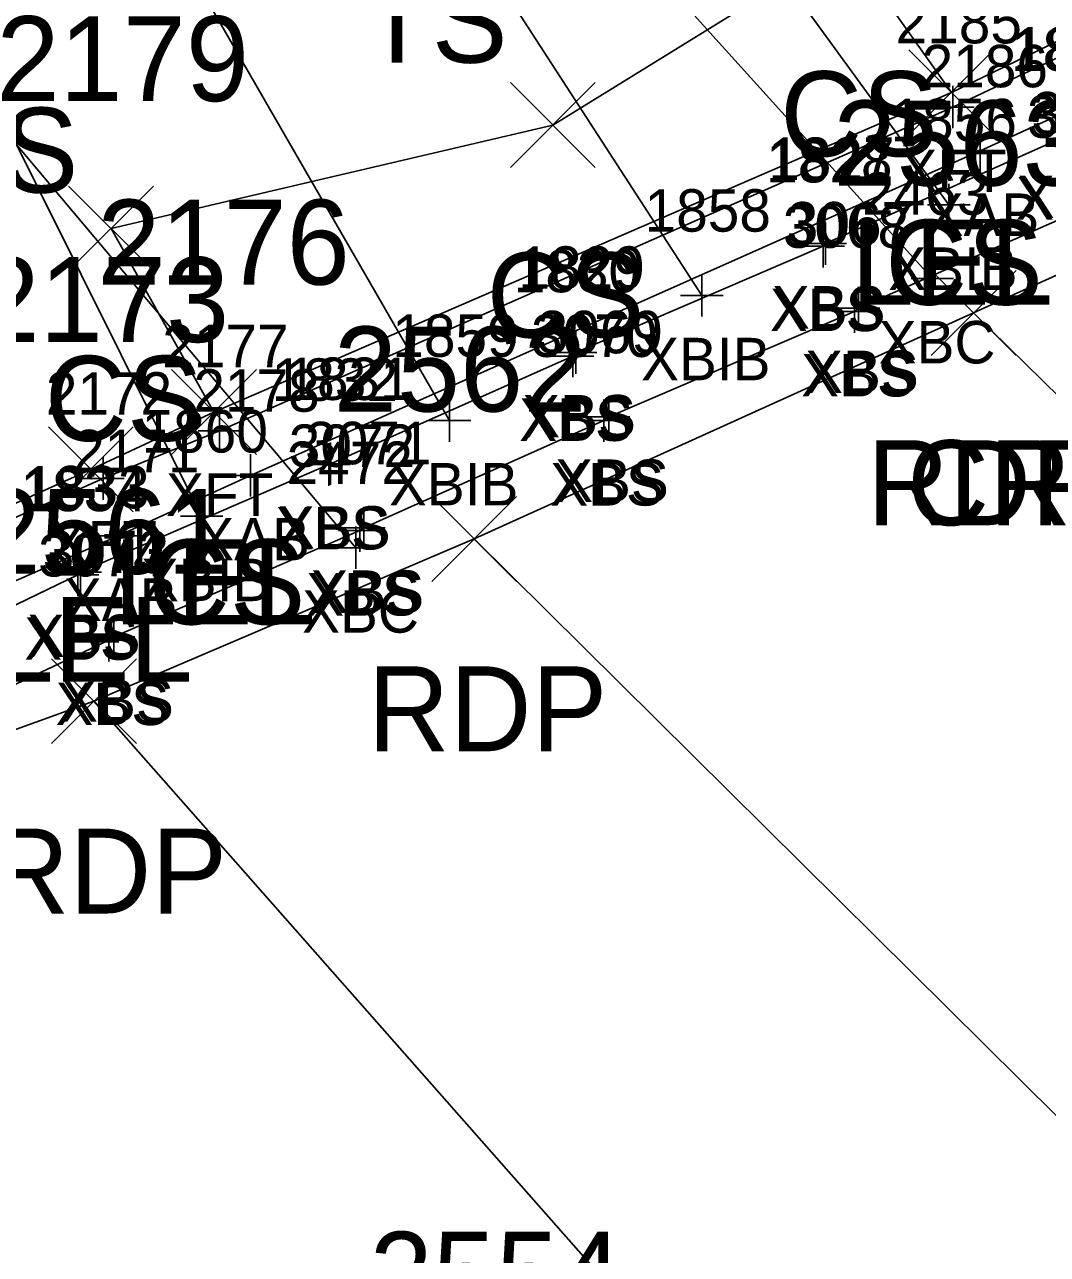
# Model space of a CAD drawing. Extents: x 1504228 to 1506103, y 437717 to 440106.
# Drawn here: x 1505241.43 to 1505265.52, y 438136.49 to 438165.45 of the extents above; entities that cross this region are included whole.
import ezdxf

# ---------------------------------------------------------------- set-up
doc = ezdxf.new("R2010")
doc.units = 0
for name, color, linetype in [('B_A', 7, 'Continuous'), ('B_I', 7, 'Continuous'), ('B_TIC', 7, 'Continuous'), ('BB', 7, 'Continuous'), ('BELB', 7, 'Continuous'), ('BFT', 7, 'Continuous'), ('BSE', 7, 'Continuous'), ('BSUBM', 7, 'Continuous'), ('L_A', 7, 'Continuous'), ('L_I', 7, 'Continuous'), ('L_TIC', 7, 'Continuous'), ('LARO', 7, 'Continuous'), ('LELB', 7, 'Continuous'), ('P_A', 7, 'Continuous'), ('P_I', 7, 'Continuous'), ('P_TIC', 7, 'Continuous'), ('PET', 7, 'Continuous'), ('PRC', 7, 'Continuous')]:
    doc.layers.add(name, color=color, linetype=linetype)

msp = doc.modelspace()

# ---------------------------------------------------------------- linework, layer by layer
at = {"layer": 'B_TIC'}
for p, q in [((1505263.294, 438163.511), (1505263.37, 438163.511)), ((1505263.935, 438162.477), (1505264.01, 438162.477)), ((1505263.201, 438161.205), (1505263.277, 438161.205)), ((1505260.245, 438160.235), (1505260.32, 438160.235)), ((1505260.292, 438160.295), (1505260.368, 438160.295)), ((1505262.812, 438159.474), (1505262.887, 438159.474)), ((1505257.382, 438159.077), (1505257.458, 438159.077)), ((1505261.076, 438158.776), (1505261.152, 438158.776)), ((1505260.982, 438158.696), (1505261.058, 438158.696)), ((1505254.343, 438157.649), (1505254.419, 438157.649)), ((1505254.414, 438157.731), (1505254.49, 438157.731)), ((1505255.189, 438156.213), (1505255.265, 438156.213)), ((1505246.023, 438155.885), (1505246.098, 438155.885)), ((1505251.445, 438156.129), (1505251.52, 438156.129)), ((1505255.073, 438156.127), (1505255.149, 438156.127)), ((1505248.599, 438155.093), (1505248.675, 438155.093)), ((1505248.638, 438155.113), (1505248.714, 438155.113)), ((1505243.281, 438154.766), (1505243.357, 438154.766)), ((1505246.757, 438154.837), (1505246.832, 438154.837)), ((1505245.603, 438153.876), (1505245.678, 438153.876)), ((1505249.326, 438153.537), (1505249.402, 438153.537)), ((1505249.426, 438153.6), (1505249.502, 438153.6)), ((1505243.64, 438153.412), (1505243.716, 438153.412)), ((1505249.234, 438153.134), (1505249.31, 438153.134)), ((1505242.686, 438152.495), (1505242.762, 438152.495)), ((1505242.75, 438152.562), (1505242.825, 438152.562)), ((1505243.422, 438150.958), (1505243.498, 438150.958)), ((1505243.532, 438151.037), (1505243.608, 438151.037))]:
    msp.add_line(p, q, dxfattribs=at)
for points in [[(1505263.291, 438163.011), (1505263.291, 438164.011)], [(1505262.791, 438163.511), (1505263.791, 438163.511)], [(1505263.932, 438161.977), (1505263.932, 438162.977)], [(1505263.432, 438162.477), (1505264.432, 438162.477)], [(1505263.198, 438160.705), (1505263.198, 438161.705)], [(1505262.698, 438161.205), (1505263.698, 438161.205)], [(1505260.289, 438159.795), (1505260.289, 438160.795)], [(1505260.241, 438159.735), (1505260.241, 438160.735)], [(1505259.741, 438160.235), (1505260.741, 438160.235)], [(1505259.789, 438160.295), (1505260.789, 438160.295)], [(1505262.808, 438158.974), (1505262.808, 438159.974)], [(1505257.379, 438158.577), (1505257.379, 438159.577)], [(1505262.308, 438159.474), (1505263.308, 438159.474)], [(1505256.879, 438159.077), (1505257.879, 438159.077)], [(1505260.979, 438158.196), (1505260.979, 438159.196)], [(1505261.073, 438158.276), (1505261.073, 438159.276)], [(1505260.573, 438158.776), (1505261.573, 438158.776)], [(1505260.479, 438158.696), (1505261.479, 438158.696)], [(1505254.411, 438157.231), (1505254.411, 438158.231)], [(1505254.34, 438157.149), (1505254.34, 438158.149)], [(1505253.84, 438157.649), (1505254.84, 438157.649)], [(1505253.911, 438157.731), (1505254.911, 438157.731)], [(1505251.441, 438155.629), (1505251.441, 438156.629)], [(1505255.07, 438155.627), (1505255.07, 438156.627)], [(1505255.186, 438155.713), (1505255.186, 438156.713)], [(1505246.019, 438155.385), (1505246.019, 438156.385)], [(1505254.686, 438156.213), (1505255.686, 438156.213)], [(1505245.519, 438155.885), (1505246.519, 438155.885)], [(1505250.941, 438156.129), (1505251.941, 438156.129)], [(1505254.57, 438156.127), (1505255.57, 438156.127)], [(1505248.596, 438154.593), (1505248.596, 438155.593)], [(1505248.635, 438154.613), (1505248.635, 438155.613)], [(1505246.753, 438154.337), (1505246.753, 438155.337)], [(1505243.278, 438154.266), (1505243.278, 438155.266)], [(1505248.096, 438155.093), (1505249.096, 438155.093)], [(1505248.135, 438155.113), (1505249.135, 438155.113)], [(1505242.778, 438154.766), (1505243.778, 438154.766)], [(1505246.253, 438154.837), (1505247.253, 438154.837)], [(1505245.599, 438153.376), (1505245.599, 438154.376)], [(1505243.637, 438152.912), (1505243.637, 438153.912)], [(1505245.099, 438153.876), (1505246.099, 438153.876)], [(1505249.323, 438153.037), (1505249.323, 438154.037)], [(1505249.423, 438153.1), (1505249.423, 438154.1)], [(1505248.823, 438153.537), (1505249.823, 438153.537)], [(1505248.923, 438153.6), (1505249.923, 438153.6)], [(1505249.231, 438152.634), (1505249.231, 438153.634)], [(1505243.137, 438153.412), (1505244.137, 438153.412)], [(1505242.683, 438151.995), (1505242.683, 438152.995)], [(1505242.746, 438152.062), (1505242.746, 438153.062)], [(1505248.731, 438153.134), (1505249.731, 438153.134)], [(1505242.183, 438152.495), (1505243.183, 438152.495)], [(1505242.246, 438152.562), (1505243.246, 438152.562)], [(1505243.529, 438150.537), (1505243.529, 438151.537)], [(1505243.419, 438150.458), (1505243.419, 438151.458)], [(1505242.919, 438150.958), (1505243.919, 438150.958)], [(1505243.029, 438151.037), (1505244.029, 438151.037)]]:
    msp.add_lwpolyline(points, dxfattribs=at)
at = {"layer": 'BB'}
for points in [[(1505263.198, 438161.205), (1505236.12, 438198.358)], [(1505257.379, 438159.077), (1505232.798, 438197.013)], [(1505251.441, 438156.129), (1505228.857, 438195.264)], [(1505245.599, 438153.876), (1505225.746, 438193.733)]]:
    msp.add_lwpolyline(points, dxfattribs=at)
at = {"layer": 'BELB'}
for points in [[(1505262.808, 438159.474), (1505244.884, 438179.311), (1505229.042, 438198.247), (1505213.306, 438219.16), (1505200.113, 438237.757)], [(1505189.093, 438232.07), (1505202.074, 438213.317), (1505217.089, 438192.519), (1505234.002, 438171.224), (1505249.231, 438153.134)]]:
    msp.add_lwpolyline(points, dxfattribs=at)
at = {"layer": 'BFT'}
msp.add_lwpolyline([(1505211.711, 438138.978), (1505211.593, 438140.8), (1505215.376, 438142.417), (1505230.303, 438149.002), (1505243.278, 438154.766), (1505246.019, 438155.885), (1505263.291, 438163.511), (1505271.064, 438167.183), (1505276.649, 438169.866), (1505288.201, 438174.699), (1505288.73, 438173.49)], dxfattribs=at)
at = {"layer": 'BSE'}
for points in [[(1505266.037, 438162.863), (1505260.289, 438160.295), (1505260.241, 438160.235), (1505254.411, 438157.731), (1505254.34, 438157.649), (1505248.635, 438155.113), (1505248.596, 438155.093), (1505242.746, 438152.562), (1505242.683, 438152.495), (1505239.318, 438150.871)], [(1505266.757, 438161.287), (1505261.073, 438158.776), (1505260.979, 438158.696), (1505255.186, 438156.213), (1505255.07, 438156.127), (1505249.423, 438153.6), (1505249.323, 438153.537), (1505243.529, 438151.037), (1505243.419, 438150.958), (1505240.07, 438149.38)]]:
    msp.add_lwpolyline(points, dxfattribs=at)
at = {"layer": 'BSUBM'}
msp.add_lwpolyline([(1505214.761, 438127.389), (1505213.65, 438134.809), (1505212.657, 438139.975), (1505231.134, 438147.944), (1505243.637, 438153.412), (1505246.753, 438154.837), (1505263.932, 438162.477), (1505271.425, 438165.886), (1505277.465, 438168.561), (1505287.974, 438173.167), (1505291.052, 438171.05), (1505297.268, 438166.649), (1505302.136, 438162.984), (1505307.468, 438159.403), (1505307.306, 438158.962)], dxfattribs=at)
at = {"layer": 'L_TIC'}
for points in [[(1505262.257, 438162.856), (1505264.257, 438164.856)], [(1505264.257, 438162.856), (1505262.257, 438164.856)], [(1505262.257, 438162.856), (1505264.257, 438164.856)], [(1505264.257, 438162.856), (1505262.257, 438164.856)], [(1505252.871, 438162.088), (1505254.871, 438164.088)], [(1505254.871, 438162.088), (1505252.871, 438164.088)], [(1505242.468, 438159.651), (1505244.468, 438161.651)], [(1505244.468, 438159.651), (1505242.468, 438161.651)], [(1505244.889, 438155.33), (1505246.889, 438157.33)], [(1505246.889, 438155.33), (1505244.889, 438157.33)], [(1505244.889, 438155.33), (1505246.889, 438157.33)], [(1505246.889, 438155.33), (1505244.889, 438157.33)], [(1505241.992, 438153.978), (1505243.992, 438155.978)], [(1505243.992, 438153.978), (1505241.992, 438155.978)]]:
    msp.add_lwpolyline(points, dxfattribs=at)
at = {"layer": 'LARO'}
msp.add_lwpolyline([(1505211.067, 438140.867), (1505215.631, 438142.954), (1505229.653, 438148.999), (1505242.992, 438154.978), (1505245.889, 438156.33), (1505263.257, 438163.856), (1505270.634, 438167.43), (1505277.265, 438170.598), (1505281.289, 438172.305), (1505281.518, 438175.58), (1505285.106, 438180.489), (1505287.419, 438180.921)], dxfattribs=at)
at = {"layer": 'LELB'}
msp.add_lwpolyline([(1505245.889, 438156.33), (1505243.468, 438160.651), (1505253.871, 438163.088), (1505260.782, 438167.353), (1505263.257, 438163.856)], dxfattribs=at)
at = {"layer": 'P_TIC'}
for points in [[(1505262.781, 438157.664), (1505264.781, 438159.664)], [(1505264.781, 438157.664), (1505262.781, 438159.664)], [(1505262.781, 438157.664), (1505264.781, 438159.664)], [(1505264.781, 438157.664), (1505262.781, 438159.664)], [(1505251.019, 438152.342), (1505253.019, 438154.342)], [(1505253.019, 438152.342), (1505251.019, 438154.342)], [(1505251.019, 438152.342), (1505253.019, 438154.342)], [(1505253.019, 438152.342), (1505251.019, 438154.342)], [(1505242.065, 438148.521), (1505244.065, 438150.521)], [(1505244.065, 438148.521), (1505242.065, 438150.521)], [(1505242.065, 438148.521), (1505244.065, 438150.521)], [(1505244.065, 438148.521), (1505242.065, 438150.521)]]:
    msp.add_lwpolyline(points, dxfattribs=at)
at = {"layer": 'PET'}
for points in [[(1505219.541, 438139.332), (1505229.478, 438143.453), (1505236.137, 438147.016), (1505243.065, 438149.521), (1505252.019, 438153.342), (1505263.781, 438158.664), (1505277.038, 438164.677), (1505295.889, 438147.093), (1505311.676, 438134.175), (1505338.301, 438109.134), (1505363.246, 438092.977), (1505381.83, 438081.07), (1505419.293, 438061.963), (1505441.952, 438049.929), (1505474.016, 438032.73)], [(1505276.045, 438129.534), (1505252.019, 438153.342)], [(1505261.662, 438128.655), (1505259.103, 438131.337), (1505243.065, 438149.521)]]:
    msp.add_lwpolyline(points, dxfattribs=at)
at = {"layer": 'PRC'}
msp.add_lwpolyline([(1505263.781, 438158.664), (1505284.158, 438138.68), (1505307.093, 438117.221), (1505329.521, 438100.507), (1505353.091, 438084.687), (1505386.556, 438065.64), (1505412.799, 438050.856), (1505435.687, 438038.531), (1505467.608, 438021.56)], dxfattribs=at)

# ---------------------------------------------------------------- texts
at = {"layer": 'B_A'}
for s, p in [('XFT', (1505262.035, 438161.511)), ('XBS', (1505264.777, 438160.863)), ('XBS', (1505264.801, 438160.896)), ('XAB', (1505262.652, 438160.477)), ('XBIB', (1505261.769, 438159.205)), ('XBS', (1505258.982, 438158.235)), ('XBS', (1505259.029, 438158.295)), ('XBC', (1505261.544, 438157.474)), ('XBIB', (1505255.95, 438157.077)), ('XBS', (1505259.719, 438156.696)), ('XBS', (1505259.813, 438156.776)), ('XBS', (1505253.151, 438155.731)), ('XBS', (1505253.08, 438155.649)), ('XBIB', (1505250.012, 438154.129)), ('XBS', (1505253.81, 438154.127)), ('XBS', (1505253.926, 438154.213)), ('XFT', (1505244.763, 438153.885)), ('XBS', (1505247.375, 438153.113)), ('XAB', (1505245.474, 438152.837)), ('XBS', (1505247.336, 438153.093)), ('XFT', (1505242.022, 438152.766)), ('XBIB', (1505244.17, 438151.876)), ('XAB', (1505242.357, 438151.412)), ('XBS', (1505248.063, 438151.537)), ('XBS', (1505248.163, 438151.6)), ('XBC', (1505247.967, 438151.134)), ('XBS', (1505241.423, 438150.495)), ('XBS', (1505241.486, 438150.562)), ('XBS', (1505242.159, 438148.958)), ('XBS', (1505242.269, 438149.037))]:
    msp.add_text(s, height=1, dxfattribs=at).set_placement(p)
at = {"layer": 'B_I'}
for s, p in [('2185', (1505261.944, 438165.011)), ('1825', (1505264.714, 438164.396)), ('1826', (1505264.663, 438164.363)), ('2186', (1505262.557, 438163.977)), ('1856', (1505261.824, 438162.705)), ('3066', (1505265.037, 438162.787)), ('3065', (1505265.144, 438162.867)), ('1827', (1505258.943, 438161.795)), ('1828', (1505258.895, 438161.735)), ('2463', (1505261.154, 438160.974)), ('1858', (1505256.032, 438160.577)), ('3068', (1505259.286, 438160.196)), ('3067', (1505259.38, 438160.276)), ('1829', (1505253.06, 438159.231)), ('1830', (1505252.95, 438159.149)), ('1859', (1505250.091, 438157.629)), ('3070', (1505253.357, 438157.627)), ('3069', (1505253.489, 438157.713)), ('2177', (1505244.673, 438157.385)), ('1832', (1505247.249, 438156.593)), ('1831', (1505247.572, 438156.613)), ('2178', (1505245.407, 438156.337)), ('2172', (1505241.931, 438156.266)), ('1860', (1505244.186, 438155.376)), ('2171', (1505242.574, 438154.912)), ('3072', (1505247.654, 438155.037)), ('3071', (1505248.037, 438155.1)), ('2472', (1505247.601, 438154.634)), ('1834', (1505241.336, 438153.995)), ('1833', (1505241.4, 438154.062)), ('3073', (1505241.86, 438152.537)), ('3074', (1505241.75, 438152.458))]:
    msp.add_text(s, height=1, dxfattribs=at).set_placement(p)
at = {"layer": 'L_A'}
for s, p in [('TS', (1505249.387, 438164.557)), ('CS', (1505259.223, 438162.353)), ('TS', (1505239.28, 438161.496)), ('LEL', (1505260.895, 438158.856)), ('CS', (1505261.698, 438158.856)), ('CS', (1505252.311, 438158.088)), ('CS', (1505241.909, 438155.651)), ('LEL', (1505243.527, 438151.33)), ('CS', (1505244.33, 438151.33)), ('LEL', (1505240.63, 438149.978))]:
    msp.add_text(s, height=2, dxfattribs=at).set_placement(p)
at = {"layer": 'L_I'}
for s, p in [('2179', (1505240.767, 438163.651)), ('2176', (1505243.141, 438159.33)), ('2176', (1505243.141, 438159.33)), ('2173', (1505240.299, 438157.978))]:
    msp.add_text(s, height=2, dxfattribs=at).set_placement(p)
at = {"layer": 'P_A'}
for s, p in [('RDP', (1505261.269, 438153.664)), ('CR', (1505262.214, 438153.664)), ('RDP', (1505249.507, 438148.342)), ('RDP', (1505249.507, 438148.342)), ('RDP', (1505240.553, 438144.521)), ('RDP', (1505240.553, 438144.521))]:
    msp.add_text(s, height=2, dxfattribs=at).set_placement(p)
at = {"layer": 'P_I'}
for s, p in [('2563', (1505260.474, 438161.664)), ('2563', (1505260.474, 438161.664)), ('2562', (1505248.712, 438156.342)), ('2562', (1505248.712, 438156.342)), ('2561', (1505240.325, 438152.521)), ('2561', (1505240.325, 438152.521)), ('2554', (1505249.555, 438135.026))]:
    msp.add_text(s, height=2, dxfattribs=at).set_placement(p)

doc.saveas('drawing.dxf')
